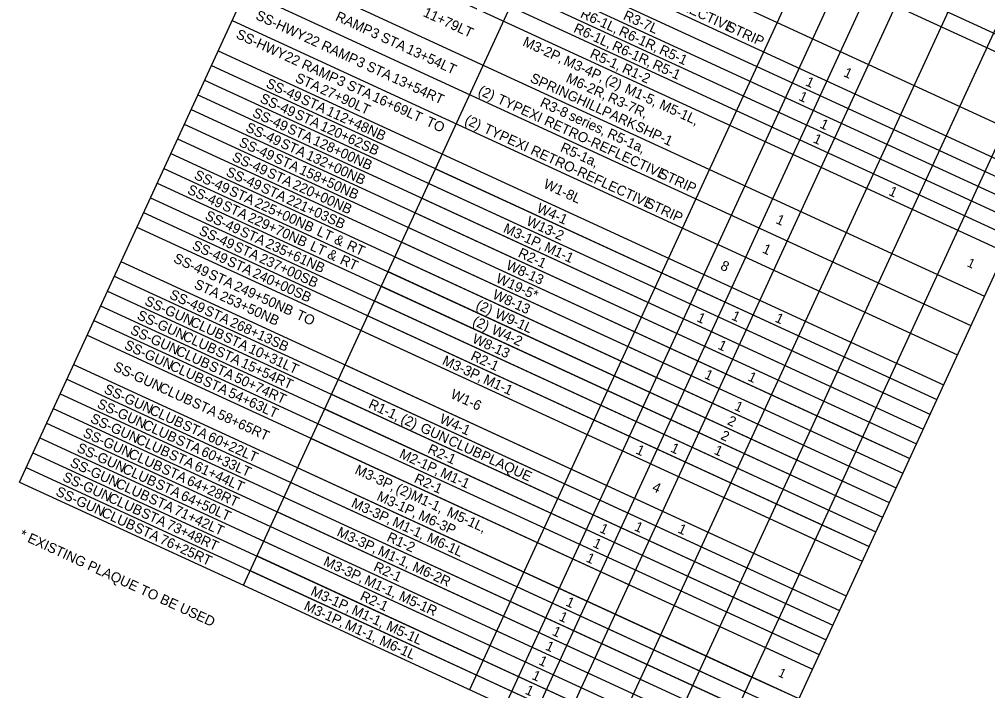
# Model space of a CAD drawing. Extents: x 627405 to 651306, y 367647 to 373471.
# Drawn here: x 650055.9 to 650493.4, y 372839.8 to 373143.2 of the extents above; entities that cross this region are included whole.
import ezdxf

# ---------------------------------------------------------------- set-up
doc = ezdxf.new("R2010")
doc.units = 0
doc.layers.add('Default', color=7, linetype='Continuous')

msp = doc.modelspace()

# ---------------------------------------------------------------- linework, layer by layer
at = {"layer": 'Default'}
for p, q in [((650055.92, 372934.12), (650303.5, 373471.4)), ((650157.2, 372887.45), (650398.97, 373412.11)), ((650259.47, 372840.32), (650501.24, 373364.98)), ((650259.47, 372840.32), (650498.03, 373358.01)), ((650275.41, 372832.97), (650513.97, 373350.66)), ((650288.03, 372827.16), (650526.59, 373344.85)), ((650300.65, 372821.34), (650539.21, 373339.03)), ((650321.24, 372811.86), (650559.79, 373329.55)), ((650341.83, 372802.37), (650580.38, 373320.06)), ((650383.67, 372783.09), (650631.25, 373320.37)), ((650362.41, 372792.88), (650597.76, 373303.6)), ((650362.41, 372792.88), (650597.76, 373303.6)), ((650210.16, 373268.84), (650537.91, 373117.81)), ((650207.1, 373262.2), (650534.85, 373111.17)), ((650194.86, 373235.63), (650522.61, 373084.6)), ((650188.74, 373222.35), (650516.49, 373071.32)), ((650185.68, 373215.71), (650513.43, 373064.68)), ((650182.62, 373209.07), (650510.37, 373058.04)), ((650179.56, 373202.43), (650507.3, 373051.4)), ((650176.5, 373195.79), (650504.24, 373044.76)), ((650173.44, 373189.14), (650501.18, 373038.12)), ((650164.26, 373169.22), (650492, 373018.19)), ((650158.13, 373155.94), (650485.88, 373004.91)), ((650152.01, 373142.66), (650479.76, 372991.63)), ((650145.74, 373129.04), (650473.49, 372978.01)), ((650142.68, 373122.4), (650470.43, 372971.37)), ((650139.62, 373115.76), (650467.37, 372964.73)), ((650136.56, 373109.12), (650464.31, 372958.09)), ((650133.5, 373102.48), (650461.25, 372951.45)), ((650130.44, 373095.83), (650458.19, 372944.81)), ((650127.38, 373089.19), (650455.13, 372938.16)), ((650124.32, 373082.55), (650452.07, 372931.52)), ((650121.26, 373075.91), (650449, 372924.88)), ((650243.96, 373075.73), (650449.18, 372981.16)), ((650118.2, 373069.27), (650445.94, 372918.24)), ((650240.9, 373069.09), (650446.11, 372974.52)), ((650115.14, 373062.63), (650442.88, 372911.6)), ((650237.84, 373062.45), (650443.05, 372967.88)), ((650112.08, 373055.99), (650439.82, 372904.96)), ((650234.78, 373055.81), (650439.99, 372961.24)), ((650109.02, 373049.35), (650436.76, 372898.32)), ((650231.72, 373049.16), (650436.93, 372954.6)), ((650228.66, 373042.52), (650433.87, 372947.96)), ((650225.6, 373035.88), (650343.81, 372981.41)), ((650101.82, 373033.74), (650429.57, 372882.71)), ((650098.76, 373027.1), (650426.51, 372876.07)), ((650222.54, 373029.24), (650427.75, 372934.67)), ((650219.48, 373022.6), (650424.69, 372928.03)), ((650095.7, 373020.46), (650423.45, 372869.43)), ((650092.64, 373013.81), (650420.39, 372862.79)), ((650216.42, 373015.96), (650421.63, 372921.39)), ((650213.36, 373009.32), (650418.57, 372914.75)), ((650089.58, 373007.17), (650417.33, 372856.14)), ((650086.52, 373000.53), (650414.27, 372849.5)), ((650210.3, 373002.67), (650415.51, 372908.11)), ((650080.4, 372987.25), (650408.15, 372836.22)), ((650203.1, 372987.07), (650408.32, 372892.5)), ((650077.34, 372980.61), (650405.09, 372829.58)), ((650200.04, 372980.43), (650405.26, 372885.86)), ((650343.81, 372981.41), (650356.43, 372975.59)), ((650449.18, 372981.16), (650470.43, 372971.37)), ((650074.28, 372973.97), (650402.03, 372822.94)), ((650196.98, 372973.79), (650402.2, 372879.22)), ((650356.43, 372975.59), (650430.81, 372941.32)), ((650446.11, 372974.52), (650467.37, 372964.73)), ((650071.22, 372967.33), (650398.97, 372816.3)), ((650193.92, 372967.14), (650399.14, 372872.58)), ((650443.05, 372967.88), (650464.31, 372958.09)), ((650068.16, 372960.68), (650395.91, 372809.66)), ((650190.86, 372960.5), (650396.08, 372865.94)), ((650439.99, 372961.24), (650461.25, 372951.45)), ((650065.1, 372954.04), (650392.85, 372803.01)), ((650187.8, 372953.86), (650393.02, 372859.3)), ((650436.93, 372954.6), (650458.19, 372944.81)), ((650062.04, 372947.4), (650389.79, 372796.37)), ((650433.87, 372947.96), (650455.13, 372938.16)), ((650058.98, 372940.76), (650386.73, 372789.73)), ((650181.68, 372940.58), (650386.9, 372846.01)), ((650430.81, 372941.32), (650452.07, 372931.52)), ((650055.92, 372934.12), (650157.2, 372887.45)), ((650178.62, 372933.94), (650383.84, 372839.37)), ((650427.75, 372934.67), (650449, 372924.88)), ((650175.56, 372927.3), (650380.78, 372832.73)), ((650424.69, 372928.03), (650445.94, 372918.24)), ((650172.5, 372920.65), (650377.72, 372826.09)), ((650421.63, 372921.39), (650442.88, 372911.6)), ((650169.44, 372914.01), (650374.66, 372819.45)), ((650418.57, 372914.75), (650439.82, 372904.96)), ((650415.51, 372908.11), (650436.76, 372898.32)), ((650166.38, 372907.37), (650371.59, 372812.81)), ((650163.32, 372900.73), (650368.53, 372806.17)), ((650160.26, 372894.09), (650365.47, 372799.52)), ((650408.32, 372892.5), (650429.57, 372882.71)), ((650157.2, 372887.45), (650362.41, 372792.88)), ((650405.26, 372885.86), (650426.51, 372876.07)), ((650402.2, 372879.22), (650423.45, 372869.43)), ((650399.14, 372872.58), (650420.39, 372862.79)), ((650396.08, 372865.94), (650417.33, 372856.14)), ((650393.02, 372859.3), (650414.27, 372849.5)), ((650386.9, 372846.01), (650408.15, 372836.22))]:
    msp.add_line(p, q, dxfattribs=at)

# ---------------------------------------------------------------- texts
for s, height, p in [(' RETRO-REFLECTIVE', 4.5, (650321.74, 373162.92)), (' 11+79LT', 4.5, (650236.49, 373145.53)), ('R6-1L,', 4.5, (650309.03, 373144.31)), ('SS-HWY', 4.5, (650162.28, 373143.5)), (' RAMP', 4.5, (650196.83, 373143.68)), ('R3-7L', 4.5, (650328.4, 373143.44)), (' 3', 4.5, (650212.77, 373136.33)), ('R6-1L,', 4.5, (650305.97, 373137.67)), (' R6-1R,', 4.5, (650324.86, 373137.02)), (' STRIP', 4.5, (650373.52, 373139.06)), ('SS-HWY', 4.5, (650153.43, 373134.99)), (' 22', 4.5, (650182.72, 373134.08)), (' STA', 4.5, (650217.28, 373134.26)), ('M3-2P,', 4.5, (650282.97, 373131.55)), (' RAMP', 4.5, (650190.36, 373130.56)), (' 13+54LT', 4.5, (650228.84, 373128.93)), (' R6-1R,', 4.5, (650321.8, 373130.38)), (' R5-1', 4.5, (650343.13, 373128.6)), (' 22', 4.5, (650173.87, 373125.57)), (' 3', 4.5, (650206.31, 373123.21)), (' M3-4P,', 4.5, (650299.94, 373123.73)), ('R5-1,', 4.5, (650313.34, 373126.22)), (' RAMP', 4.5, (650181.51, 373122.05)), (' STA', 4.5, (650210.81, 373121.14)), (' R1-2', 4.5, (650326.37, 373120.22)), (' R5-1', 4.5, (650340.07, 373121.96)), ('STA', 4.5, (650180.16, 373115.24)), (' 3', 4.5, (650197.45, 373114.7)), (' 13+54RT', 4.5, (650222.38, 373115.81)), ('SPRINGHILL', 4.5, (650286.33, 373115.13)), ('M6-2R,', 4.5, (650302.5, 373115.12)), (' (2)', 4.5, (650318.68, 373115.09)), ('1', 4.5, (650427.97, 373117.68)), ('SS-49', 4.5, (650166.97, 373112.76)), (' 27+90LT', 4.5, (650189.97, 373110.72)), (' STA', 4.5, (650201.96, 373112.63)), ('(2)', 4.5, (650262.85, 373109.54)), (' M1-5,', 4.5, (650327.51, 373111.02)), ('1', 4.5, (650410.76, 373113.54)), ('SS-49', 4.5, (650164.22, 373105.97)), (' STA', 4.5, (650181.17, 373106.21)), (' 16+69LT', 4.5, (650213.52, 373107.3)), (' TYPE', 4.5, (650269.93, 373106.28)), (' R3-7R,', 4.5, (650319.87, 373107.11)), ('1', 4.5, (650407.7, 373106.9)), ('R3-8', 4.5, (650290.8, 373104.1)), (' M5-1L,', 4.5, (650343.14, 373103.82)), ('SS-49', 4.5, (650160.84, 373099.47)), (' STA', 4.5, (650178.42, 373099.43)), (' 112+48NB', 4.5, (650192.73, 373100.88)), ('(2)', 4.5, (650256.73, 373096.26)), (' XI', 4.5, (650284.28, 373099.67)), (' series,', 4.5, (650302.26, 373098.81)), (' PARK', 4.5, (650317.12, 373100.95)), ('SS-49', 4.5, (650157.78, 373092.83)), (' STA', 4.5, (650175.05, 373092.93)), (' 120+62SB', 4.5, (650189.98, 373094.1)), (' TO', 4.5, (650237.71, 373096.15)), (' TYPE', 4.5, (650263.81, 373093)), (' RETRO-REFLECTIVE', 4.5, (650291.13, 373096.51)), (' SHP-1', 4.5, (650332.23, 373093.99)), ('1', 4.5, (650417.26, 373094.44)), (' R5-1a,', 4.5, (650319.63, 373090.81)), ('1', 4.5, (650414.2, 373087.8)), ('SS-49', 4.5, (650154.72, 373086.19)), (' STA', 4.5, (650171.99, 373086.29)), (' 128+00NB', 4.5, (650186.61, 373087.6)), (' XI', 4.5, (650278.16, 373086.39)), ('R5-1a,', 4.5, (650299.97, 373083.77)), ('SS-49', 4.5, (650151.66, 373079.55)), (' STA', 4.5, (650168.93, 373079.65)), (' 132+00NB', 4.5, (650183.55, 373080.96)), (' RETRO-REFLECTIVE', 4.5, (650285.01, 373083.23)), ('SS-49', 4.5, (650134.5, 373071.35)), ('SS-49', 4.5, (650148.91, 373072.77)), (' STA', 4.5, (650165.86, 373073.01)), (' 158+50NB', 4.5, (650180.49, 373074.32)), (' STRIP', 4.5, (650342.92, 373072.65)), (' 220+00NB', 4.5, (650177.43, 373067.68)), ('W1-8L', 4.5, (650292.34, 373067.26)), ('SS-49', 4.5, (650131.44, 373064.71)), (' STA', 4.5, (650148.71, 373064.81)), (' STA', 4.5, (650163.12, 373066.22)), ('1', 4.5, (650448.33, 373064.02)), (' STA', 4.5, (650145.65, 373058.17)), (' 225+00NB', 4.5, (650160.27, 373059.48)), (' 221+03SB', 4.5, (650174.68, 373060.89)), (' STRIP', 4.5, (650336.79, 373059.36)), ('SS-49', 4.5, (650139.42, 373052.99)), ('W4-1', 4.5, (650289.29, 373056.39)), (' 229+70NB', 4.5, (650157.21, 373052.84)), ('W13-2', 4.5, (650284.6, 373050.5)), ('1', 4.5, (650397.37, 373051.27)), ('SS-49', 4.5, (650136.67, 373046.2)), (' STA', 4.5, (650153.62, 373046.44)), (' LT', 4.5, (650188.39, 373046.52)), ('M3-1P,', 4.5, (650274.17, 373047.25)), ('SS-49', 4.5, (650133.61, 373039.56)), (' 235+61NB', 4.5, (650165.19, 373041.11)), (' LT', 4.5, (650185.33, 373039.88)), (' &', 4.5, (650196.22, 373042.91)), (' RT', 4.5, (650201.94, 373040.28)), (' STA', 4.5, (650150.87, 373039.66)), (' &', 4.5, (650193.16, 373036.27)), ('R2-1', 4.5, (650280.9, 373036.1)), (' M1-1', 4.5, (650291.15, 373039.43)), ('1', 4.5, (650391.25, 373037.99)), ('SS-49', 4.5, (650125.17, 373033.68)), (' STA', 4.5, (650147.81, 373033.02)), (' 237+00SB', 4.5, (650162.44, 373034.33)), (' RT', 4.5, (650198.88, 373033.64)), ('W8-13', 4.5, (650275.45, 373030.56)), ('1', 4.13, (650483.77, 373031.79)), (' STA', 4.5, (650139.37, 373027.13)), (' 240+00SB', 4.5, (650159.38, 373027.69)), ('8', 4.5, (650372.31, 373030.41)), (' STA', 4.5, (650132.99, 373022.65)), ('W19-5*', 4.5, (650270.85, 373024.63)), (' 249+50NB', 4.5, (650150.94, 373021.81)), ('W8-13', 4.5, (650269.33, 373017.28)), ('SS-GUN', 4.5, (650112.12, 373014.44)), ('SS-49', 4.5, (650123.36, 373017.31)), (' 253+50NB', 4.5, (650144.55, 373017.32)), (' STA', 4.5, (650137.56, 373010.77)), ('(2)', 4.5, (650261.84, 373012.68)), (' W9-1L', 4.5, (650268.91, 373009.42)), ('SS-GUN', 4.5, (650108.71, 373007.96)), (' CLUB', 4.5, (650131.19, 373005.65)), (' 268+13SB', 4.5, (650149.13, 373005.44)), (' TO', 4.5, (650179.06, 373008.85)), ('(2)', 4.5, (650260.29, 373005.34)), ('1', 4.5, (650361.64, 373006.94)), ('1', 4.5, (650377.32, 373007.77)), ('1', 4.5, (650396.99, 373006.76)), ('SS-GUN', 4.5, (650105.65, 373001.32)), (' W4-2', 4.5, (650267.37, 373002.08)), (' CLUB', 4.5, (650127.79, 372999.17)), (' STA', 4.5, (650145.99, 372998.83)), ('W8-13', 4.5, (650260.15, 372997.35)), ('SS-GUN', 4.5, (650102.93, 372994.52)), (' CLUB', 4.5, (650124.73, 372992.53)), (' STA', 4.5, (650142.58, 372992.35)), (' 10+31LT', 4.5, (650157.56, 372993.5)), ('1', 4.5, (650371.2, 372994.49)), ('M3-3P,', 4.5, (650246.63, 372987.48)), ('R2-1', 4.5, (650259.48, 372989.61)), ('SS-GUN', 4.5, (650098, 372984.71)), (' CLUB', 4.5, (650122.01, 372985.73)), (' STA', 4.5, (650139.52, 372985.71)), (' 15+54RT', 4.5, (650154.15, 372987.02)), (' STA', 4.5, (650136.81, 372978.91)), (' 50+74RT', 4.5, (650151.09, 372980.38)), (' M1-1', 4.5, (650263.61, 372979.66)), ('1', 4.5, (650365.08, 372981.21)), ('1', 4.5, (650384.75, 372980.2)), ('SS-GUN', 4.5, (650093.75, 372974.59)), (' CLUB', 4.5, (650117.08, 372975.92)), (' 54+63LT', 4.5, (650148.37, 372973.58)), ('W1-6', 4.5, (650250.37, 372972.27)), ('SS-GUN', 4.5, (650090.69, 372967.95)), (' CLUB', 4.5, (650112.83, 372965.8)), (' STA', 4.5, (650131.87, 372969.1)), ('R1-1,', 4.5, (650213.28, 372967.82)), ('1', 4.5, (650378.62, 372966.91)), ('SS-GUN', 4.5, (650087.63, 372961.31)), (' 58+65RT', 4.5, (650143.44, 372963.78)), (' (2)', 4.5, (650226.32, 372961.82)), ('W4-1', 4.5, (650245.38, 372961.09)), (' CLUB', 4.5, (650109.77, 372959.16)), (' STA', 4.5, (650127.63, 372958.98)), (' GUN', 4.5, (650235.15, 372957.75)), ('2', 4.5, (650375.46, 372960.32)), ('SS-GUN', 4.5, (650084.23, 372954.83)), (' 60+22LT', 4.5, (650139.19, 372953.65)), ('2', 4.5, (650372.4, 372953.68)), ('SS-GUN', 4.5, (650081.51, 372948.03)), (' CLUB', 4.5, (650106.71, 372952.52)), (' STA', 4.5, (650124.57, 372952.34)), ('R2-1', 4.5, (650240.04, 372947.44)), (' CLUB', 4.5, (650247.68, 372951.97)), ('1', 4.5, (650349.78, 372948)), (' CLUB', 4.5, (650103.3, 372946.04)), (' STA', 4.5, (650121.51, 372945.7)), (' 60+33LT', 4.5, (650136.13, 372947.01)), ('M2-1P,', 4.5, (650227.2, 372945.31)), (' PLAQUE', 4.5, (650262.48, 372945.15)), ('1', 4.5, (650334.1, 372947.17)), ('1', 4.5, (650369.44, 372946.99)), ('SS-GUN', 4.5, (650078.45, 372941.39)), (' 61+44LT', 4.5, (650133.07, 372940.37)), ('SS-GUN', 4.5, (650075.05, 372934.9)), (' CLUB', 4.5, (650100.59, 372939.24)), (' STA', 4.5, (650118.1, 372939.22)), ('M3-3P,', 4.5, (650207.15, 372938.13)), ('R2-1', 4.5, (650233.92, 372934.16)), (' M1-1', 4.5, (650244.17, 372937.48)), (' CLUB', 4.5, (650097.53, 372932.6)), (' STA', 4.5, (650115.39, 372932.42)), (' 64+28RT', 4.5, (650129.67, 372933.89)), ('SS-GUN', 4.5, (650071.99, 372928.26)), (' 64+50LT', 4.5, (650126.95, 372927.09)), (' M3-1P,', 4.5, (650215.53, 372926.84)), (' (2)M1-1,', 4.5, (650224.12, 372930.31)), ('4', 4.5, (650341.44, 372930.31)), (' CLUB', 4.5, (650094.12, 372926.11)), (' STA', 4.5, (650112.33, 372925.78)), ('M3-3P,', 4.5, (650205.52, 372923.09)), (' CLUB', 4.5, (650091.06, 372919.47)), (' STA', 4.5, (650108.92, 372919.3)), (' 71+42LT', 4.5, (650123.89, 372920.45)), (' M6-3P', 4.5, (650234.26, 372918.21)), (' M5-1L,', 4.5, (650247.13, 372919.71)), (' 73+48RT', 4.5, (650120.49, 372913.97)), (' M1-1,', 4.5, (650222.5, 372915.27)), ('* EXISTING PLAQUE TO BE USED', 4.5, (650055.57, 372908.88)), (' STA', 4.5, (650105.86, 372912.65)), ('M3-3P,', 4.5, (650199, 372909.99)), ('1', 4.5, (650317.73, 372911.64)), ('1', 4.5, (650333.41, 372912.47)), ('1', 4.5, (650353.07, 372911.46)), (' 76+25RT', 4.5, (650117.43, 372907.32)), ('R1-2', 4.5, (650221.58, 372907.64)), (' M6-1L', 4.5, (650238.13, 372908.06)), ('1', 4.5, (650314.67, 372905)), (' M1-1,', 4.5, (650215.98, 372902.17)), ('M3-3P,', 4.5, (650192.88, 372896.71)), ('1', 4.5, (650311.61, 372898.36)), ('R2-1', 4.5, (650215.56, 372894.31)), (' M6-2R', 4.5, (650231.61, 372894.96)), (' M1-1,', 4.5, (650209.86, 372888.88)), ('M3-1P,', 4.5, (650187.16, 372883.24)), ('R2-1', 4.5, (650209.44, 372881.03)), (' M5-1R', 4.5, (650225.49, 372881.68)), ('1', 4.5, (650302.43, 372878.43)), ('M3-1P,', 4.5, (650184.1, 372876.6)), (' M1-1,', 4.5, (650204.14, 372875.42)), ('1', 4.5, (650299.37, 372871.79)), (' M1-1,', 4.5, (650201.07, 372868.78)), (' M5-1L', 4.5, (650219.77, 372868.22)), ('1', 4.5, (650296.31, 372865.15)), (' M6-1L', 4.5, (650216.71, 372861.57)), ('1', 4.5, (650293.25, 372858.51)), ('1', 4.5, (650290.19, 372851.87)), ('1', 4.5, (650287.12, 372845.23)), ('1', 4.13, (650398.39, 372846.5)), ('1', 4.5, (650284.06, 372838.59))]:
    msp.add_text(s, height=height, rotation=335.2593, dxfattribs=at).set_placement(p)

doc.saveas('drawing.dxf')
